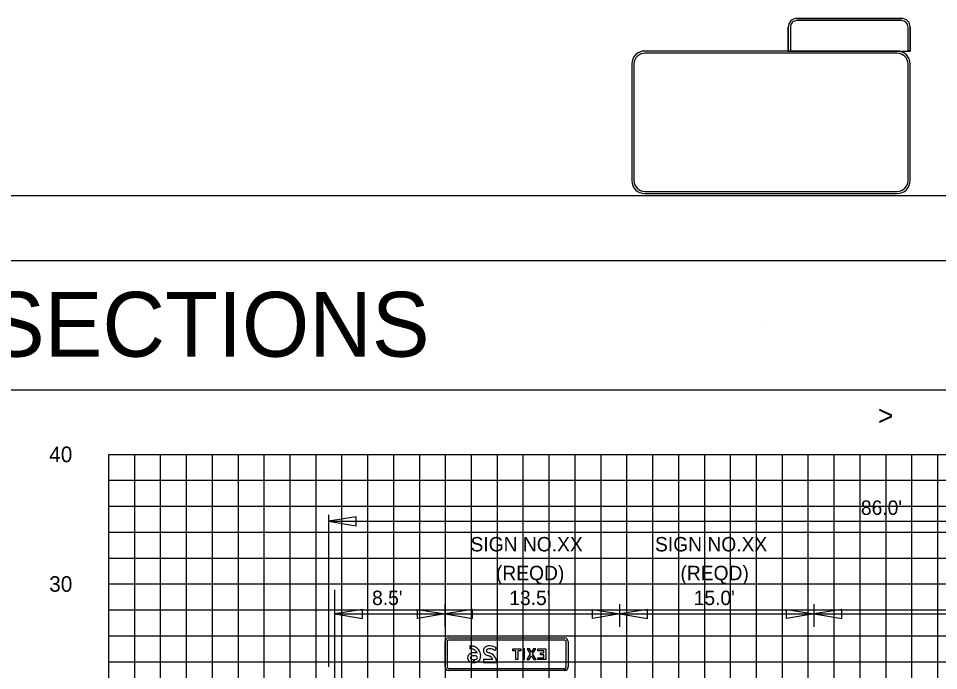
# Model space of a CAD drawing. Extents: x 2193008 to 2198143, y 1236112 to 1237864.
# Drawn here: x 2195321.7 to 2195392.7, y 1237301.4 to 1237351.7 of the extents above; entities that cross this region are included whole.
import ezdxf

# ---------------------------------------------------------------- set-up
doc = ezdxf.new("R2010")
doc.units = 0
for name, color, linetype in [('3', 7, 'Continuous'), ('31', 7, 'Continuous'), ('60', 7, 'Continuous'), ('ANNO-SHT', 7, 'Continuous'), ('DRAINAGE', 7, 'Continuous'), ('GSBWFILL', 7, 'Continuous'), ('GSCOLORFILL', 7, 'Continuous'), ('GSDIMS', 7, 'Continuous'), ('GSOUTLINE', 7, 'Continuous'), ('Level 1', 7, 'Continuous'), ('Level 55', 7, 'Continuous'), ('Level 62', 7, 'Continuous'), ('SHT-BDR', 7, 'Continuous'), ('SHT-BNDRY', 7, 'Continuous')]:
    doc.layers.add(name, color=color, linetype=linetype)

# ---------------------------------------------------------------- blocks, each defined once
blk = doc.blocks.new('SC47208')
at = {"layer": 'Level 1'}
blk.add_line((0, 0), (0, 0), dxfattribs=at)

msp = doc.modelspace()

# ---------------------------------------------------------------- linework, layer by layer
msp.add_line((2195346.092, 1237300.108), (2195346.092, 1237307.648))
at = {"layer": '3'}
for p, q in [((2195345.592, 1237313.437), (2195345.592, 1237301.72)), ((2195345.592, 1237312.95), (2195431.649, 1237312.95))]:
    msp.add_line(p, q, dxfattribs=at)
at = {"layer": '60'}
msp.add_line((2195328.632, 1237258.106), (2195328.632, 1237318.106), dxfattribs=at)
at = {"layer": 'GSBWFILL'}
for points in [[(2195356.503, 1237303.333), (2195356.503, 1237303.108)], [(2195358.42, 1237302.97), (2195358.565, 1237303.142)], [(2195356.801, 1237302.265), (2195356.801, 1237302.04)], [(2195356.801, 1237302.04), (2195356.801, 1237302.265)], [(2195358.29, 1237302.286), (2195357.553, 1237302.286), (2195357.553, 1237302.061), (2195358.565, 1237302.061)]]:
    msp.add_lwpolyline(points, dxfattribs=at)
for points in [[(2195360.44, 1237302.953), (2195360.203, 1237302.953), (2195360.203, 1237302.27), (2195360.053, 1237302.27), (2195360.053, 1237302.953), (2195359.815, 1237302.953), (2195359.815, 1237303.103), (2195360.44, 1237303.103)], [(2195360.732, 1237302.27), (2195360.732, 1237303.103), (2195360.582, 1237303.103), (2195360.582, 1237302.27)], [(2195361.076, 1237302.27), (2195361.261, 1237302.565), (2195361.446, 1237302.27), (2195361.623, 1237302.27), (2195361.349, 1237302.706), (2195361.598, 1237303.103), (2195361.421, 1237303.103), (2195361.261, 1237302.847), (2195361.101, 1237303.103), (2195360.923, 1237303.103), (2195361.172, 1237302.706), (2195360.898, 1237302.27)], [(2195361.74, 1237302.42), (2195362.215, 1237302.42), (2195362.215, 1237302.644), (2195361.969, 1237302.644), (2195361.969, 1237302.794), (2195362.215, 1237302.794), (2195362.215, 1237302.953), (2195361.753, 1237302.953), (2195361.753, 1237303.103), (2195362.365, 1237303.103), (2195362.365, 1237302.27), (2195361.74, 1237302.27)]]:
    msp.add_lwpolyline(points, close=True, dxfattribs=at)
for centre, major_axis, start_param, end_param in [((2195356.503, 1237301.981), (0, -1.352), 3.007438, 3.141593), ((2195356.587, 1237302.598), (0, -0.73), 2.503122, 3.007438), ((2195357.958, 1237302.864), (0, -0.458), 3.401668, 3.717847), ((2195358.043, 1237302.543), (0, -0.79), 3.141593, 3.401668), ((2195358.043, 1237302.527), (0, -0.807), 2.437833, 3.141593), ((2195356.68, 1237302.421), (0, -0.352), 4.186921, 4.712389), ((2195356.665, 1237302.43), (0, -0.335), 3.790286, 4.186921), ((2195356.757, 1237302.309), (0, -0.487), 3.334761, 3.790282), ((2195356.503, 1237301.981), (0, -1.127), 3.007438, 3.141593), ((2195356.757, 1237302.309), (0, -0.262), 3.334763, 3.790278), ((2195356.587, 1237302.598), (0, -0.505), 2.503122, 3.007438), ((2195356.822, 1237301.973), (0, -0.829), 2.831599, 3.334759), ((2195356.822, 1237301.973), (0, -0.604), 2.831599, 3.334759), ((2195356.49, 1237302.467), (0, -0.668), 2.281348, 2.503131), ((2195356.543, 1237302.553), (0, -0.572), 1.946387, 2.228676), ((2195356.49, 1237302.467), (0, -0.893), 2.274779, 2.503129), ((2195356.543, 1237302.553), (0, -0.797), 1.570796, 2.236187), ((2195357.894, 1237302.962), (0, -0.342), 3.717847, 4.712389), ((2195357.902, 1237302.962), (0, -0.349), 4.712389, 5.798451), ((2195358.172, 1237303.475), (0, -0.929), 5.798451, 6.032655), ((2195357.894, 1237302.962), (0, -0.117), 3.717847, 4.712389), ((2195357.902, 1237302.962), (0, -0.124), 4.712389, 5.798451), ((2195357.958, 1237302.864), (0, -0.233), 3.401668, 3.717847), ((2195358.172, 1237303.475), (0, -0.704), 5.798451, 6.032655), ((2195358.043, 1237302.543), (0, -0.565), 3.141593, 3.401668), ((2195357.81, 1237302.061), (0, -0.53), 2.009535, 2.891063), ((2195357.81, 1237302.061), (0, -0.755), 1.570796, 2.891063), ((2195358.043, 1237302.527), (0, -0.582), 2.437833, 3.141593), ((2195356.667, 1237302.421), (0, -0.34), 4.712389, 5.195335), ((2195356.729, 1237302.47), (0, -0.417), 5.230268, 5.909903), ((2195356.68, 1237302.421), (0, -0.127), 4.186921, 4.712389), ((2195356.667, 1237302.421), (0, -0.115), 4.712389, 5.163692), ((2195356.729, 1237302.47), (0, -0.192), 5.252339, 5.909908), ((2195356.665, 1237302.43), (0, -0.11), 3.790286, 4.186921), ((2195356.801, 1237302.654), (0, -0.615), 5.909899, 6.283134), ((2195356.801, 1237302.654), (0, -0.39), 5.909899, 6.283105), ((2195356.801, 1237302.719), (0, -0.454), 0, 0.317835), ((2195356.801, 1237302.719), (0, -0.679), 0, 0.317835), ((2195356.857, 1237302.548), (0, -0.274), 0.317835, 0.837468), ((2195356.965, 1237302.436), (0, -0.119), 0.925029, 2.790003), ((2195356.857, 1237302.548), (0, -0.499), 0.317835, 0.837468), ((2195356.93, 1237302.483), (0, -0.402), 0.837468, 1.392674), ((2195356.674, 1237302.553), (0, -0.666), 1.356974, 1.570796)]:
    msp.add_ellipse(centre, major_axis=major_axis, ratio=0.999994, start_param=start_param, end_param=end_param, dxfattribs=at)
at = {"layer": 'GSCOLORFILL'}
for p, q in [((2195354.59, 1237301.703), (2195354.59, 1237303.67)), ((2195354.757, 1237303.67), (2195354.757, 1237301.703)), ((2195354.861, 1237303.941), (2195363.828, 1237303.941)), ((2195363.828, 1237303.774), (2195354.861, 1237303.774)), ((2195363.932, 1237301.703), (2195363.932, 1237303.67)), ((2195364.098, 1237303.67), (2195364.098, 1237301.703)), ((2195354.861, 1237301.599), (2195363.826, 1237301.599)), ((2195363.826, 1237301.432), (2195354.861, 1237301.432)), ((2195363.826, 1237301.599), (2195363.826, 1237301.432)), ((2195363.828, 1237301.432), (2195363.828, 1237301.599))]:
    msp.add_line(p, q, dxfattribs=at)
for points in [[(2195356.503, 1237303.333), (2195356.503, 1237303.108)], [(2195358.42, 1237302.97), (2195358.565, 1237303.142)], [(2195356.801, 1237302.265), (2195356.801, 1237302.04)], [(2195356.801, 1237302.04), (2195356.801, 1237302.265)], [(2195358.29, 1237302.286), (2195357.553, 1237302.286), (2195357.553, 1237302.061), (2195358.565, 1237302.061)]]:
    msp.add_lwpolyline(points, dxfattribs=at)
for points in [[(2195360.44, 1237302.953), (2195360.203, 1237302.953), (2195360.203, 1237302.27), (2195360.053, 1237302.27), (2195360.053, 1237302.953), (2195359.815, 1237302.953), (2195359.815, 1237303.103), (2195360.44, 1237303.103)], [(2195360.732, 1237302.27), (2195360.732, 1237303.103), (2195360.582, 1237303.103), (2195360.582, 1237302.27)], [(2195361.076, 1237302.27), (2195361.261, 1237302.565), (2195361.446, 1237302.27), (2195361.623, 1237302.27), (2195361.349, 1237302.706), (2195361.598, 1237303.103), (2195361.421, 1237303.103), (2195361.261, 1237302.847), (2195361.101, 1237303.103), (2195360.923, 1237303.103), (2195361.172, 1237302.706), (2195360.898, 1237302.27)], [(2195361.74, 1237302.42), (2195362.215, 1237302.42), (2195362.215, 1237302.644), (2195361.969, 1237302.644), (2195361.969, 1237302.794), (2195362.215, 1237302.794), (2195362.215, 1237302.953), (2195361.753, 1237302.953), (2195361.753, 1237303.103), (2195362.365, 1237303.103), (2195362.365, 1237302.27), (2195361.74, 1237302.27)]]:
    msp.add_lwpolyline(points, close=True, dxfattribs=at)
for centre, radius, start, end in [((2195354.861, 1237303.67), 0.271, 90, 180), ((2195354.861, 1237303.67), 0.104, 90, 180), ((2195363.828, 1237303.67), 0.271, 0, 90), ((2195363.828, 1237303.67), 0.104, 0, 90), ((2195354.861, 1237301.703), 0.271, 180, 270), ((2195354.861, 1237301.703), 0.104, 180, 270), ((2195363.828, 1237301.703), 0.271, 270, 0), ((2195363.828, 1237301.703), 0.104, 270, 0)]:
    msp.add_arc(centre, radius, start, end, dxfattribs=at)
for centre, major_axis, start_param, end_param in [((2195356.503, 1237301.981), (0, -1.352), 3.007438, 3.141593), ((2195356.587, 1237302.598), (0, -0.73), 2.503122, 3.007438), ((2195357.958, 1237302.864), (0, -0.458), 3.401668, 3.717847), ((2195358.043, 1237302.543), (0, -0.79), 3.141593, 3.401668), ((2195358.043, 1237302.527), (0, -0.807), 2.437833, 3.141593), ((2195356.68, 1237302.421), (0, -0.352), 4.186921, 4.712389), ((2195356.665, 1237302.43), (0, -0.335), 3.790286, 4.186921), ((2195356.757, 1237302.309), (0, -0.487), 3.334761, 3.790282), ((2195356.503, 1237301.981), (0, -1.127), 3.007438, 3.141593), ((2195356.757, 1237302.309), (0, -0.262), 3.334763, 3.790278), ((2195356.587, 1237302.598), (0, -0.505), 2.503122, 3.007438), ((2195356.822, 1237301.973), (0, -0.829), 2.831599, 3.334759), ((2195356.822, 1237301.973), (0, -0.604), 2.831599, 3.334759), ((2195356.49, 1237302.467), (0, -0.668), 2.281348, 2.503131), ((2195356.543, 1237302.553), (0, -0.572), 1.946387, 2.228676), ((2195356.49, 1237302.467), (0, -0.893), 2.274779, 2.503129), ((2195356.543, 1237302.553), (0, -0.797), 1.570796, 2.236187), ((2195357.894, 1237302.962), (0, -0.342), 3.717847, 4.712389), ((2195357.902, 1237302.962), (0, -0.349), 4.712389, 5.798451), ((2195358.172, 1237303.475), (0, -0.929), 5.798451, 6.032655), ((2195357.894, 1237302.962), (0, -0.117), 3.717847, 4.712389), ((2195357.902, 1237302.962), (0, -0.124), 4.712389, 5.798451), ((2195357.958, 1237302.864), (0, -0.233), 3.401668, 3.717847), ((2195358.172, 1237303.475), (0, -0.704), 5.798451, 6.032655), ((2195358.043, 1237302.543), (0, -0.565), 3.141593, 3.401668), ((2195357.81, 1237302.061), (0, -0.53), 2.009535, 2.891063), ((2195357.81, 1237302.061), (0, -0.755), 1.570796, 2.891063), ((2195358.043, 1237302.527), (0, -0.582), 2.437833, 3.141593), ((2195356.667, 1237302.421), (0, -0.34), 4.712389, 5.195335), ((2195356.729, 1237302.47), (0, -0.417), 5.230268, 5.909903), ((2195356.68, 1237302.421), (0, -0.127), 4.186921, 4.712389), ((2195356.667, 1237302.421), (0, -0.115), 4.712389, 5.163692), ((2195356.729, 1237302.47), (0, -0.192), 5.252339, 5.909908), ((2195356.665, 1237302.43), (0, -0.11), 3.790286, 4.186921), ((2195356.801, 1237302.654), (0, -0.615), 5.909899, 6.283134), ((2195356.801, 1237302.654), (0, -0.39), 5.909899, 6.283105), ((2195356.801, 1237302.719), (0, -0.454), 0, 0.317835), ((2195356.801, 1237302.719), (0, -0.679), 0, 0.317835), ((2195356.857, 1237302.548), (0, -0.274), 0.317835, 0.837468), ((2195356.965, 1237302.436), (0, -0.119), 0.925029, 2.790003), ((2195356.857, 1237302.548), (0, -0.499), 0.317835, 0.837468), ((2195356.93, 1237302.483), (0, -0.402), 0.837468, 1.392674), ((2195356.674, 1237302.553), (0, -0.666), 1.356974, 1.570796)]:
    msp.add_ellipse(centre, major_axis=major_axis, ratio=0.999994, start_param=start_param, end_param=end_param, dxfattribs=at)
at = {"layer": 'GSDIMS'}
for p, q in [((2195354.59, 1237304.808), (2195354.59, 1237306.549)), ((2195368.094, 1237304.808), (2195368.094, 1237306.549)), ((2195383.079, 1237304.808), (2195383.079, 1237306.549)), ((2195346.092, 1237305.791), (2195354.59, 1237305.791)), ((2195354.59, 1237305.791), (2195368.094, 1237305.791)), ((2195368.094, 1237305.791), (2195383.079, 1237305.791)), ((2195383.079, 1237305.791), (2195431.143, 1237305.791))]:
    msp.add_line(p, q, dxfattribs=at)
for points in [[(2195345.592, 1237312.95), (2195347.72, 1237312.603), (2195347.72, 1237313.298)], [(2195346.092, 1237305.791), (2195348.22, 1237305.444), (2195348.22, 1237306.139)], [(2195354.59, 1237305.791), (2195352.462, 1237305.444), (2195352.462, 1237306.139)], [(2195354.59, 1237305.791), (2195356.719, 1237305.444), (2195356.719, 1237306.139)], [(2195368.094, 1237305.791), (2195365.966, 1237305.444), (2195365.966, 1237306.139)], [(2195368.094, 1237305.791), (2195370.223, 1237305.444), (2195370.223, 1237306.139)], [(2195383.079, 1237305.791), (2195380.951, 1237305.444), (2195380.951, 1237306.139)], [(2195383.079, 1237305.791), (2195385.208, 1237305.444), (2195385.208, 1237306.139)]]:
    msp.add_lwpolyline(points, close=True, dxfattribs=at)
at = {"layer": 'GSOUTLINE'}
for p, q in [((2195381.748, 1237351.732), (2195389.829, 1237351.732)), ((2195389.829, 1237351.732), (2195381.748, 1237351.732)), ((2195381.082, 1237349.217), (2195381.082, 1237351.066)), ((2195381.082, 1237351.066), (2195381.082, 1237349.217)), ((2195381.248, 1237351.066), (2195381.248, 1237349.383)), ((2195389.829, 1237351.566), (2195381.748, 1237351.566)), ((2195390.329, 1237349.383), (2195390.329, 1237351.066)), ((2195390.495, 1237351.066), (2195390.495, 1237349.217)), ((2195390.495, 1237349.217), (2195390.495, 1237351.066)), ((2195389.496, 1237349.217), (2195370.002, 1237349.217)), ((2195389.496, 1237349.05), (2195370.002, 1237349.05)), ((2195381.248, 1237349.217), (2195381.082, 1237349.217)), ((2195381.082, 1237349.217), (2195390.495, 1237349.217)), ((2195381.248, 1237349.383), (2195381.248, 1237349.217)), ((2195390.329, 1237349.217), (2195390.329, 1237349.383)), ((2195390.495, 1237349.217), (2195390.329, 1237349.217)), ((2195369.002, 1237348.217), (2195369.002, 1237339.222)), ((2195369.169, 1237348.217), (2195369.169, 1237339.222)), ((2195390.329, 1237339.222), (2195390.329, 1237348.217)), ((2195390.495, 1237339.222), (2195390.495, 1237348.217)), ((2195370.002, 1237338.389), (2195389.496, 1237338.389)), ((2195370.002, 1237338.222), (2195389.496, 1237338.222))]:
    msp.add_line(p, q, dxfattribs=at)
for points in [[(2195356.503, 1237303.333), (2195356.503, 1237303.108)], [(2195358.42, 1237302.97), (2195358.565, 1237303.142)], [(2195358.29, 1237302.286), (2195357.553, 1237302.286), (2195357.553, 1237302.061), (2195358.565, 1237302.061)]]:
    msp.add_lwpolyline(points, dxfattribs=at)
for points in [[(2195360.44, 1237302.953), (2195360.203, 1237302.953), (2195360.203, 1237302.27), (2195360.053, 1237302.27), (2195360.053, 1237302.953), (2195359.815, 1237302.953), (2195359.815, 1237303.103), (2195360.44, 1237303.103)], [(2195360.732, 1237302.27), (2195360.732, 1237303.103), (2195360.582, 1237303.103), (2195360.582, 1237302.27)], [(2195361.076, 1237302.27), (2195361.261, 1237302.565), (2195361.446, 1237302.27), (2195361.623, 1237302.27), (2195361.349, 1237302.706), (2195361.598, 1237303.103), (2195361.421, 1237303.103), (2195361.261, 1237302.847), (2195361.101, 1237303.103), (2195360.923, 1237303.103), (2195361.172, 1237302.706), (2195360.898, 1237302.27)], [(2195361.74, 1237302.42), (2195362.215, 1237302.42), (2195362.215, 1237302.644), (2195361.969, 1237302.644), (2195361.969, 1237302.794), (2195362.215, 1237302.794), (2195362.215, 1237302.953), (2195361.753, 1237302.953), (2195361.753, 1237303.103), (2195362.365, 1237303.103), (2195362.365, 1237302.27), (2195361.74, 1237302.27)]]:
    msp.add_lwpolyline(points, close=True, dxfattribs=at)
for centre, major_axis, ratio, start_param, end_param in [((2195381.748, 1237351.066), (0.666, 0), 0.999829, 1.570796, 3.141593), ((2195381.748, 1237351.066), (0.666, 0), 0.999829, 1.570796, 3.141593), ((2195389.829, 1237351.066), (0.666, 0), 0.999829, 0, 1.570796), ((2195389.829, 1237351.066), (0.666, 0), 0.999829, 0, 1.570796), ((2195381.748, 1237351.066), (0.5, 0), 0.999829, 1.570796, 3.141593), ((2195389.829, 1237351.066), (0.5, 0), 0.999829, 0, 1.570796), ((2195370.002, 1237348.217), (1, 0), 0.999829, 1.570796, 3.141593), ((2195370.002, 1237348.217), (0.833, 0), 0.999829, 1.570796, 3.141593), ((2195389.496, 1237348.217), (1, 0), 0.999829, 0, 1.570796), ((2195389.496, 1237348.217), (0.833, 0), 0.999829, 0, 1.570796), ((2195370.002, 1237339.222), (1, 0), 0.999829, 3.141593, 4.712389), ((2195370.002, 1237339.222), (0.833, 0), 0.999829, 3.141593, 4.712389), ((2195389.496, 1237339.222), (1, 0), 0.999829, 4.712389, 6.283185), ((2195389.496, 1237339.222), (0.833, 0), 0.999829, 4.712389, 6.283185), ((2195356.503, 1237301.981), (0, -1.352), 0.999994, 3.007438, 3.141593), ((2195356.587, 1237302.598), (0, -0.73), 0.999994, 2.503122, 3.007438), ((2195357.958, 1237302.864), (0, -0.458), 0.999994, 3.401668, 3.717847), ((2195358.043, 1237302.543), (0, -0.79), 0.999994, 3.141593, 3.401668), ((2195358.043, 1237302.527), (0, -0.807), 0.999994, 2.437833, 3.141593), ((2195356.68, 1237302.421), (0, -0.352), 0.999994, 4.186921, 4.712389), ((2195356.665, 1237302.43), (0, -0.335), 0.999994, 3.790286, 4.186921), ((2195356.757, 1237302.309), (0, -0.487), 0.999994, 3.334761, 3.790282), ((2195356.503, 1237301.981), (0, -1.127), 0.999994, 3.007438, 3.141593), ((2195356.757, 1237302.309), (0, -0.262), 0.999994, 3.334763, 3.790278), ((2195356.587, 1237302.598), (0, -0.505), 0.999994, 2.503122, 3.007438), ((2195356.822, 1237301.973), (0, -0.829), 0.999994, 2.831599, 3.334759), ((2195356.822, 1237301.973), (0, -0.604), 0.999994, 2.831599, 3.334759), ((2195356.49, 1237302.467), (0, -0.668), 0.999994, 2.281348, 2.503131), ((2195356.543, 1237302.553), (0, -0.572), 0.999994, 1.946387, 2.228676), ((2195356.49, 1237302.467), (0, -0.893), 0.999994, 2.274779, 2.503129), ((2195356.543, 1237302.553), (0, -0.797), 0.999994, 1.570796, 2.236187), ((2195357.894, 1237302.962), (0, -0.342), 0.999994, 3.717847, 4.712389), ((2195357.902, 1237302.962), (0, -0.349), 0.999994, 4.712389, 5.798451), ((2195358.172, 1237303.475), (0, -0.929), 0.999994, 5.798451, 6.032655), ((2195357.894, 1237302.962), (0, -0.117), 0.999994, 3.717847, 4.712389), ((2195357.902, 1237302.962), (0, -0.124), 0.999994, 4.712389, 5.798451), ((2195357.958, 1237302.864), (0, -0.233), 0.999994, 3.401668, 3.717847), ((2195358.172, 1237303.475), (0, -0.704), 0.999994, 5.798451, 6.032655), ((2195358.043, 1237302.543), (0, -0.565), 0.999994, 3.141593, 3.401668), ((2195357.81, 1237302.061), (0, -0.53), 0.999994, 2.009535, 2.891063), ((2195357.81, 1237302.061), (0, -0.755), 0.999994, 1.570796, 2.891063), ((2195358.043, 1237302.527), (0, -0.582), 0.999994, 2.437833, 3.141593), ((2195356.667, 1237302.421), (0, -0.34), 0.999994, 4.712389, 5.195335), ((2195356.729, 1237302.47), (0, -0.417), 0.999994, 5.230268, 5.909903), ((2195356.68, 1237302.421), (0, -0.127), 0.999994, 4.186921, 4.712389), ((2195356.667, 1237302.421), (0, -0.115), 0.999994, 4.712389, 5.163692), ((2195356.729, 1237302.47), (0, -0.192), 0.999994, 5.252339, 5.909908), ((2195356.665, 1237302.43), (0, -0.11), 0.999994, 3.790286, 4.186921), ((2195356.801, 1237302.654), (0, -0.615), 0.999994, 5.909899, 6.283185), ((2195356.801, 1237302.654), (0, -0.39), 0.999994, 5.909899, 6.283185), ((2195356.801, 1237302.719), (0, -0.454), 0.999994, 0, 0.317835), ((2195356.801, 1237302.719), (0, -0.679), 0.999994, 0, 0.317835), ((2195356.857, 1237302.548), (0, -0.274), 0.999994, 0.317835, 0.837468), ((2195356.965, 1237302.436), (0, -0.119), 0.999994, 0.925029, 2.790003), ((2195356.857, 1237302.548), (0, -0.499), 0.999994, 0.317835, 0.837468), ((2195356.93, 1237302.483), (0, -0.402), 0.999994, 0.837468, 1.392674), ((2195356.674, 1237302.553), (0, -0.666), 0.999994, 1.356974, 1.570796)]:
    msp.add_ellipse(centre, major_axis=major_axis, ratio=ratio, start_param=start_param, end_param=end_param, dxfattribs=at)
at = {"layer": 'Level 62'}
for p, q in [((2195328.632, 1237258.106), (2195328.632, 1237318.106)), ((2195328.632, 1237318.106), (2195448.632, 1237318.106)), ((2195330.632, 1237258.106), (2195330.632, 1237318.106)), ((2195332.632, 1237258.106), (2195332.632, 1237318.106)), ((2195334.632, 1237258.106), (2195334.632, 1237318.106)), ((2195336.632, 1237258.106), (2195336.632, 1237318.106)), ((2195338.632, 1237258.106), (2195338.632, 1237318.106)), ((2195340.632, 1237258.106), (2195340.632, 1237318.106)), ((2195342.632, 1237258.106), (2195342.632, 1237318.106)), ((2195344.632, 1237258.106), (2195344.632, 1237318.106)), ((2195346.632, 1237258.106), (2195346.632, 1237318.106)), ((2195348.632, 1237258.106), (2195348.632, 1237318.106)), ((2195350.632, 1237258.106), (2195350.632, 1237318.106)), ((2195352.632, 1237258.106), (2195352.632, 1237318.106)), ((2195354.632, 1237258.106), (2195354.632, 1237318.106)), ((2195356.632, 1237258.106), (2195356.632, 1237318.106)), ((2195358.632, 1237258.106), (2195358.632, 1237318.106)), ((2195360.632, 1237258.106), (2195360.632, 1237318.106)), ((2195362.632, 1237258.106), (2195362.632, 1237318.106)), ((2195364.632, 1237258.106), (2195364.632, 1237318.106)), ((2195366.632, 1237258.106), (2195366.632, 1237318.106)), ((2195368.632, 1237258.106), (2195368.632, 1237318.106)), ((2195370.632, 1237258.106), (2195370.632, 1237318.106)), ((2195372.632, 1237258.106), (2195372.632, 1237318.106)), ((2195374.632, 1237258.106), (2195374.632, 1237318.106)), ((2195376.632, 1237258.106), (2195376.632, 1237318.106)), ((2195378.632, 1237258.106), (2195378.632, 1237318.106)), ((2195380.632, 1237258.106), (2195380.632, 1237318.106)), ((2195382.632, 1237258.106), (2195382.632, 1237318.106)), ((2195384.632, 1237258.106), (2195384.632, 1237318.106)), ((2195386.632, 1237258.106), (2195386.632, 1237318.106)), ((2195388.632, 1237258.106), (2195388.632, 1237318.106)), ((2195390.632, 1237258.106), (2195390.632, 1237318.106)), ((2195392.632, 1237258.106), (2195392.632, 1237318.106)), ((2195328.632, 1237316.106), (2195448.632, 1237316.106)), ((2195328.632, 1237314.106), (2195448.632, 1237314.106)), ((2195328.632, 1237312.106), (2195448.632, 1237312.106)), ((2195328.632, 1237310.106), (2195448.632, 1237310.106)), ((2195328.632, 1237308.106), (2195448.632, 1237308.106)), ((2195328.632, 1237306.106), (2195448.632, 1237306.106)), ((2195328.632, 1237304.106), (2195448.632, 1237304.106)), ((2195328.632, 1237302.106), (2195448.632, 1237302.106))]:
    msp.add_line(p, q, dxfattribs=at)
msp.add_lwpolyline([(2195203.786, 1237118.036), (2195543.786, 1237118.036), (2195543.786, 1237338.036), (2195203.786, 1237338.036)], close=True, dxfattribs=at)
at = {"layer": 'SHT-BDR'}
msp.add_lwpolyline([(2195228.783, 1237133.046), (2195528.783, 1237133.046), (2195528.783, 1237323.046), (2195228.783, 1237323.046)], close=True, dxfattribs=at)
at = {"layer": 'SHT-BNDRY'}
msp.add_lwpolyline([(2195216.286, 1237123.036), (2195538.786, 1237123.036), (2195538.786, 1237333.036), (2195216.286, 1237333.036)], close=True, dxfattribs=at)

# ---------------------------------------------------------------- block references
at = {"layer": 'DRAINAGE', "xscale": 0.20000000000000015, "yscale": 0.20000000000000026, "rotation": -116.41666666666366}
msp.add_blockref('SC47208', (2195379.104, 1237328.234), dxfattribs=at)
msp.add_blockref('SC47208', (2195379.104, 1237328.234), dxfattribs=at)

# ---------------------------------------------------------------- texts
at = {"layer": '31'}
for s, p in [('40', (2195324.031, 1237317.506)), ('30', (2195324.031, 1237307.506))]:
    msp.add_text(s, height=1.2, dxfattribs=at).set_placement(p)
at = {"layer": '60'}
msp.add_text('>', height=1.5, dxfattribs=at).set_placement((2195388.024, 1237320.356))
at = {"layer": 'ANNO-SHT'}
msp.add_text('              ITS CROSS SECTIONS               ', height=4.9995, rotation=360, dxfattribs=at).set_placement((2195255.325, 1237325.638))
at = {"layer": 'Level 55'}
for s, p in [("86.0'", (2195386.691, 1237313.437)), ('SIGN NO.XX', (2195356.554, 1237310.619)), ('SIGN NO.XX', (2195370.799, 1237310.619)), ('(REQD)', (2195358.517, 1237308.398)), ('(REQD)', (2195372.762, 1237308.398)), ("8.5'", (2195348.957, 1237306.48)), ("13.5'", (2195359.549, 1237306.48)), ("15.0'", (2195373.783, 1237306.48))]:
    msp.add_text(s, height=1.1105, dxfattribs=at).set_placement(p)

doc.saveas('drawing.dxf')
